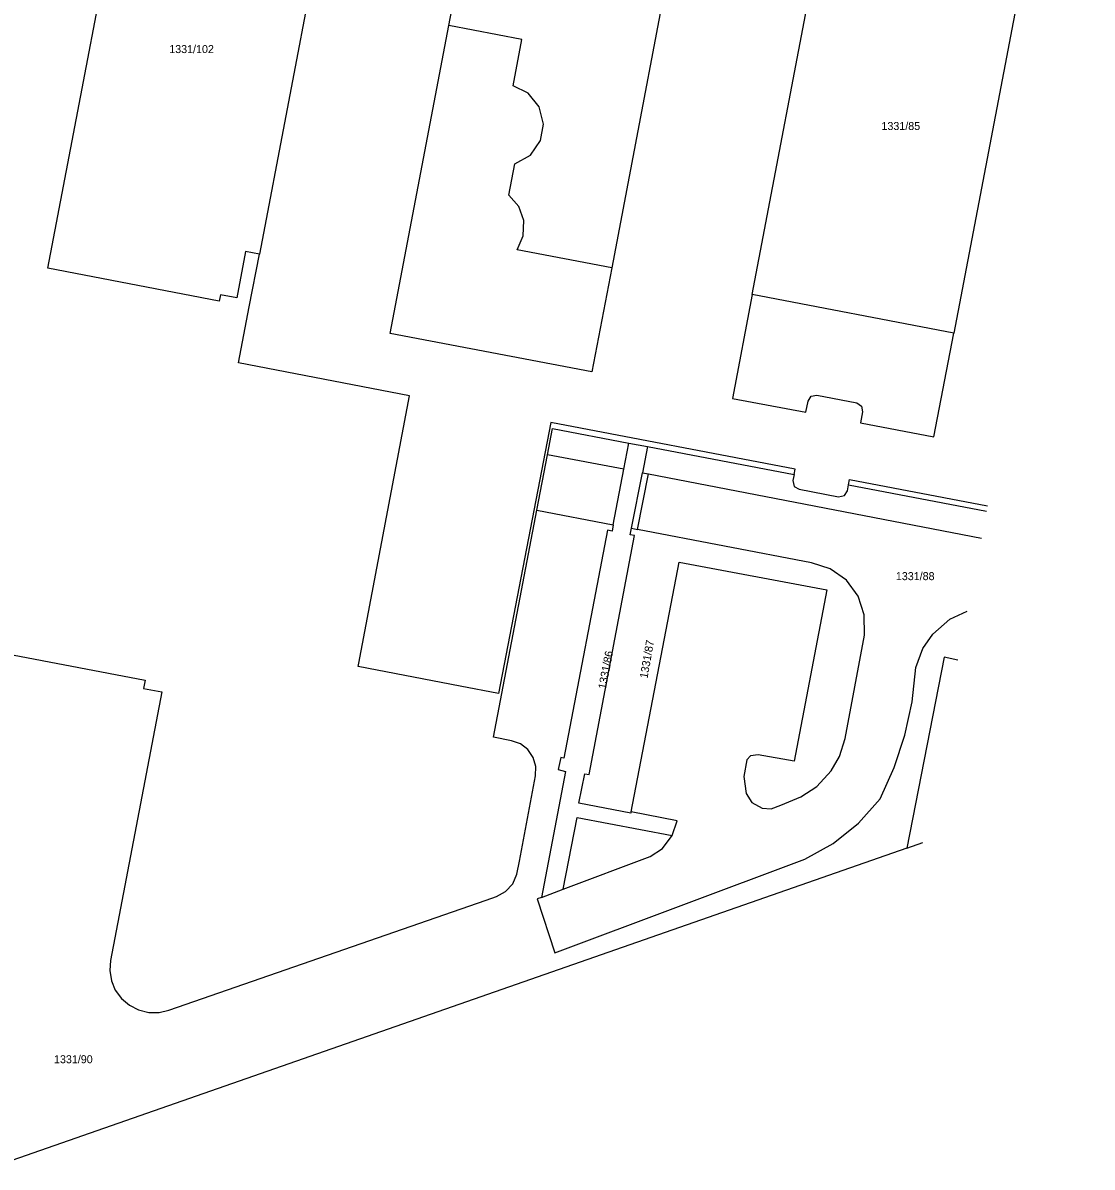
# Model space of a CAD drawing. Extents: x -601602 to -600882, y -1162594 to -1161950.
# Drawn here: x -601036.2 to -600922.6, y -1162543.8 to -1162422.3 of the extents above; entities that cross this region are included whole.
import ezdxf

# ---------------------------------------------------------------- set-up
doc = ezdxf.new("R2010")
doc.units = 0
for name, color, linetype in [('KN_Hranice parcel', 7, 'Continuous'), ('KN_Parcelní čísla', 7, 'Continuous'), ('KN_Vnitřní kresba', 7, 'Continuous')]:
    doc.layers.add(name, color=color, linetype=linetype)

msp = doc.modelspace()

# ---------------------------------------------------------------- linework, layer by layer
at = {"layer": 'KN_Hranice parcel'}
for p, q in [((-600972.36, -1162469.73), (-600980.48, -1162468.2)), ((-600973.49, -1162475.62), (-600972.36, -1162469.73)), ((-600970.93, -1162476.11), (-600969.76, -1162470.22)), ((-600969.76, -1162470.22), (-600934.4, -1162477.05)), ((-600981.6, -1162474.06), (-600973.49, -1162475.62)), ((-600942.32, -1162509.97), (-601039.44, -1162543.83))]:
    msp.add_line(p, q, dxfattribs=at)
for points in [[(-601002.25, -1162400.56), (-601011.08, -1162446.88), (-601012.55, -1162446.6), (-601013.49, -1162451.52), (-601015.21, -1162451.21), (-601015.34, -1162451.87), (-601033.55, -1162448.37), (-601024.3, -1162399.99), (-601023.63, -1162397.23), (-601022.71, -1162396.3), (-601022.67, -1162395.01), (-601023.55, -1162394.04), (-601024.83, -1162393.95), (-601028.06, -1162395.07), (-601029.47, -1162395.31), (-601029.83, -1162395.24)], [(-600965.88, -1162407.47), (-600973.66, -1162448.32), (-600983.69, -1162446.41), (-600983.05, -1162444.93), (-600983, -1162443.32), (-600983.52, -1162441.83), (-600984.57, -1162440.61), (-600983.94, -1162437.3), (-600982.3, -1162436.36), (-600981.21, -1162434.83), (-600980.89, -1162433.08), (-600981.37, -1162431.23), (-600982.54, -1162429.8), (-600984.14, -1162429.01), (-600983.2, -1162424.1), (-600990.96, -1162422.62), (-600987.95, -1162406.86)], [(-600922.64, -1162415.72), (-600929.54, -1162414.43), (-600937.33, -1162455.26), (-600958.73, -1162451.15), (-600951.62, -1162413.83), (-600951.09, -1162411.34), (-600950.04, -1162410.59), (-600949.69, -1162409.41), (-600950.1, -1162408.24), (-600951.13, -1162407.58), (-600952.35, -1162407.66), (-600956.85, -1162409.18), (-600957.58, -1162409.04)], [(-600980.48, -1162468.2), (-600979.94, -1162465.39), (-600971.83, -1162466.94), (-600969.85, -1162467.31)], [(-600969.85, -1162467.31), (-600970.4, -1162470.1), (-600969.76, -1162470.22)], [(-600969.85, -1162467.31), (-600954.29, -1162470.28), (-600954.41, -1162470.91), (-600954.27, -1162471.54), (-600953.76, -1162471.85), (-600949.58, -1162472.67), (-600948.95, -1162472.52), (-600948.63, -1162472.02), (-600948.5, -1162471.38), (-600933.85, -1162474.17)], [(-601041.22, -1162488.68), (-601023.2, -1162492.12), (-601023.37, -1162492.99), (-601021.45, -1162493.37), (-601026.88, -1162521.88), (-601026.97, -1162522.96), (-601026.8, -1162524.04), (-601026.38, -1162525.04), (-601025.73, -1162525.92), (-601024.89, -1162526.63), (-601023.92, -1162527.14), (-601022.83, -1162527.4), (-601021.73, -1162527.42), (-601020.68, -1162527.18), (-600986.99, -1162515.48), (-600985.9, -1162515.09), (-600984.93, -1162514.56), (-600984.16, -1162513.76), (-600983.74, -1162512.73), (-600983.46, -1162511.35), (-600981.74, -1162502.28), (-600981.71, -1162501.28), (-600982, -1162500.33), (-600982.55, -1162499.49), (-600983.33, -1162498.87), (-600984.29, -1162498.55), (-600986.21, -1162498.17), (-600981.6, -1162474.06)], [(-600973.49, -1162475.62), (-600973.62, -1162476.3), (-600974.11, -1162476.2), (-600978.75, -1162500.41), (-600979.05, -1162500.34), (-600979.36, -1162501.62), (-600978.57, -1162501.81), (-600981.12, -1162515.2)], [(-600971.58, -1162506.12), (-600971.63, -1162506.26), (-600977.15, -1162505.2), (-600976.52, -1162502.06), (-600976.07, -1162502.14), (-600971.25, -1162476.75), (-600971.69, -1162476.69), (-600971.55, -1162475.99), (-600970.93, -1162476.11)], [(-600971.58, -1162506.12), (-600966.48, -1162479.58), (-600950.8, -1162482.53), (-600954.27, -1162500.73), (-600958.11, -1162500.05), (-600958.91, -1162500.14), (-600959.3, -1162500.58), (-600959.63, -1162502.34), (-600959.38, -1162504.17), (-600958.78, -1162505.11), (-600957.67, -1162505.71), (-600956.73, -1162505.78), (-600955.68, -1162505.38), (-600953.58, -1162504.51), (-600951.88, -1162503.42), (-600950.34, -1162501.76), (-600949.47, -1162500.23), (-600948.87, -1162498.31), (-600946.82, -1162487.34), (-600946.83, -1162485.2), (-600947.49, -1162483.19), (-600948.74, -1162481.5), (-600950.45, -1162480.29), (-600952.45, -1162479.66), (-600970.93, -1162476.11)], [(-600981.12, -1162515.2), (-600981.57, -1162515.34), (-600979.7, -1162521.07), (-600953.15, -1162511.12), (-600950.14, -1162509.48), (-600947.44, -1162507.32), (-600945.13, -1162504.74), (-600943.65, -1162501.39), (-600942.52, -1162497.96), (-600941.75, -1162494.43), (-600941.35, -1162490.78), (-600940.62, -1162488.76), (-600939.57, -1162487.22), (-600937.73, -1162485.63), (-600935.89, -1162484.78)], [(-600936.89, -1162489.99), (-600938.36, -1162489.69), (-600942.32, -1162509.97)], [(-600981.12, -1162515.2), (-600978.81, -1162514.31), (-600969.56, -1162510.86), (-600968.28, -1162510), (-600967.25, -1162508.61), (-600966.7, -1162507.06), (-600971.58, -1162506.12)], [(-600942.32, -1162509.97), (-600940.61, -1162509.37)]]:
    msp.add_lwpolyline(points, dxfattribs=at)
at = {"layer": 'KN_Vnitřní kresba'}
for p, q in [((-601012.15, -1162452.48), (-601011.08, -1162446.88)), ((-601013.29, -1162458.44), (-601012.15, -1162452.48)), ((-600972.36, -1162469.73), (-600971.83, -1162466.94)), ((-600981.6, -1162474.06), (-600980.48, -1162468.2)), ((-600971.55, -1162475.99), (-600970.4, -1162470.1))]:
    msp.add_line(p, q, dxfattribs=at)
for points in [[(-600973.66, -1162448.32), (-600975.77, -1162459.37), (-600997.2, -1162455.3), (-600990.96, -1162422.62)], [(-600958.73, -1162451.15), (-600960.84, -1162462.22), (-600953.04, -1162463.68), (-600952.81, -1162462.49), (-600952.48, -1162461.97), (-600951.87, -1162461.84), (-600947.64, -1162462.66), (-600947.13, -1162463.01), (-600947.03, -1162463.61), (-600947.23, -1162464.81), (-600939.43, -1162466.29), (-600937.33, -1162455.26)], [(-601000.51, -1162490.31), (-600995.13, -1162461.92), (-601013.29, -1162458.44)], [(-600954.29, -1162470.28), (-600954.18, -1162469.71), (-600980.14, -1162464.76), (-600985.67, -1162493.53), (-600989.76, -1162492.75)], [(-600948.5, -1162471.38), (-600948.39, -1162470.82), (-600933.74, -1162473.61)], [(-600989.76, -1162492.75), (-601000.58, -1162490.68), (-601000.51, -1162490.31)], [(-600978.81, -1162514.31), (-600977.33, -1162506.7), (-600967.25, -1162508.61)]]:
    msp.add_lwpolyline(points, dxfattribs=at)

# ---------------------------------------------------------------- texts
at = {"layer": 'KN_Parcelní čísla'}
for s, p in [('1331/102', (-601020.65, -1162425.53)), ('1331/85', (-600945.01, -1162433.7)), ('1331/88', (-600943.48, -1162481.5)), ('1331/90', (-601032.89, -1162532.8))]:
    msp.add_text(s, height=0.85, dxfattribs=at).set_placement(p)
for s, rotation, p in [('1331/87', 80, (-600969.86, -1162491.99)), ('1331/86', 79, (-600974.28, -1162493.13))]:
    msp.add_text(s, height=0.85, rotation=rotation, dxfattribs=at).set_placement(p)

doc.saveas('drawing.dxf')
